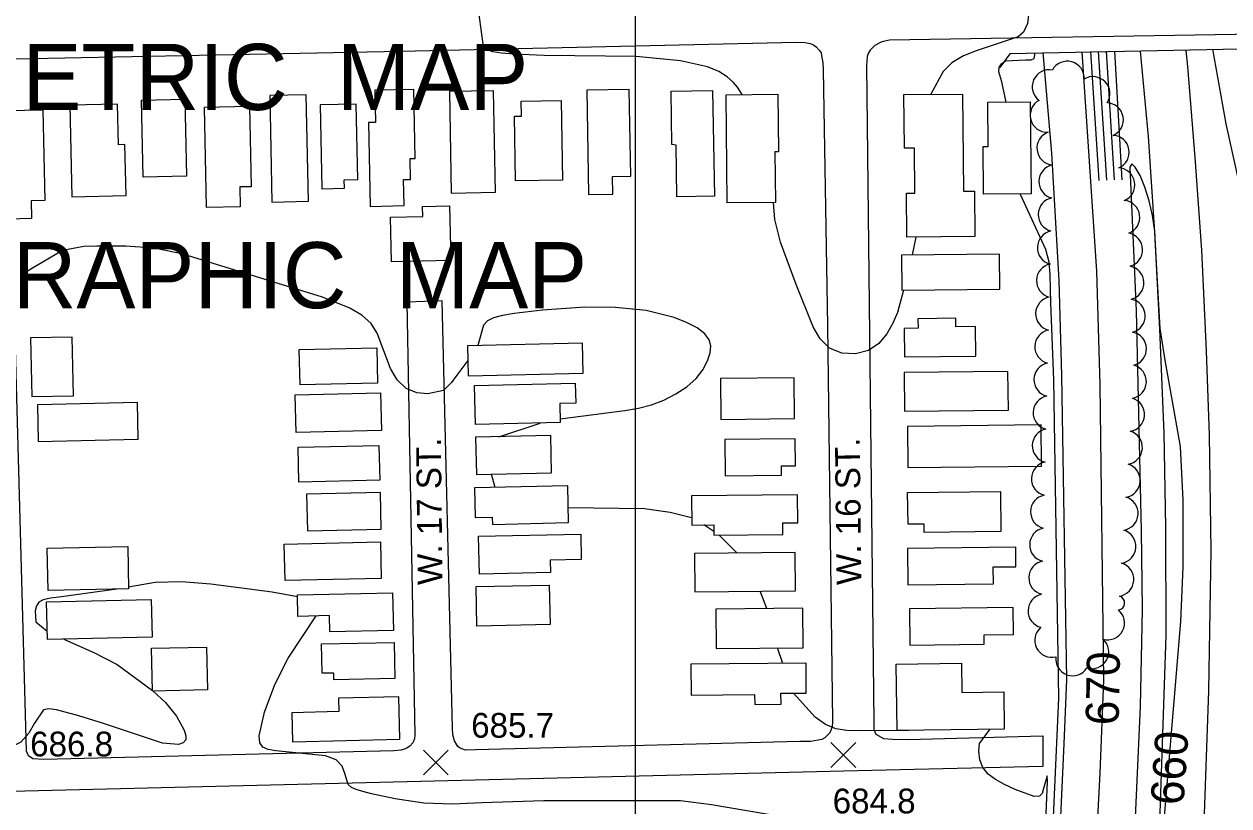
# Model space of a CAD drawing. Extents: x 79600 to 91800, y 75600 to 84400.
# Drawn here: x 85630 to 86359, y 78239 to 78712 of the extents above; entities that cross this region are included whole.
import ezdxf

# ---------------------------------------------------------------- set-up
doc = ezdxf.new("R2010")
doc.units = 0
for name, color, linetype in [('080-085$0$TI_PLAN', 7, 'Continuous'), ('080-085$0$TI_TOPO', 7, 'Continuous'), ('080-090$0$BLDG', 7, 'Continuous'), ('080-090$0$BRIDGE', 7, 'Continuous'), ('080-090$0$GRID', 7, 'Continuous'), ('080-090$0$INDEX', 7, 'Continuous'), ('080-090$0$INDXLBL', 7, 'Continuous'), ('080-090$0$INTER', 7, 'Continuous'), ('080-090$0$INTERSTATE', 7, 'Continuous'), ('080-090$0$ROAD', 7, 'Continuous'), ('080-090$0$ROAD-NAME', 7, 'Continuous'), ('080-090$0$SPOTMARK', 7, 'Continuous'), ('080-090$0$SPOTS', 7, 'Continuous'), ('080-090$0$TREES', 7, 'Continuous')]:
    doc.layers.add(name, color=color, linetype=linetype)

# ---------------------------------------------------------------- blocks, each defined once
blk = doc.blocks.new('080-090$0$SPOTS')
at = {"layer": '080-090$0$SPOTMARK'}
for p, q in [((-0.5, -0.5), (0.5, 0.5)), ((-0.5, 0.5), (0.5, -0.5))]:
    blk.add_line(p, q, dxfattribs=at)

msp = doc.modelspace()

# ---------------------------------------------------------------- linework, layer by layer
at = {"layer": '080-090$0$BLDG'}
for points in [[(85702.18, 78619.28), (85701.16, 78665.91), (85727.35, 78666.48), (85728.38, 78619.86)], [(85802.21, 78604.7), (85800.91, 78669.22), (85778.78, 78668.77), (85780.08, 78604.26)], [(85842.82, 78652.41), (85838.51, 78652.31), (85839.64, 78601.61), (85860.17, 78602.07), (85859.82, 78617.82), (85864.03, 78617.92), (85863.75, 78630.63), (85866.84, 78630.69), (85865.91, 78672.48), (85842.38, 78671.96)], [(85915.35, 78610.18), (85914.31, 78671.67), (85887.55, 78671.22), (85888.59, 78609.73)], [(85986.48, 78609.04), (85986.3, 78619.7), (85997.26, 78619.89), (85996.37, 78672.48), (85970.7, 78672.05), (85971.77, 78608.79)], [(86025.2, 78607.48), (86024.68, 78638.74), (86022.23, 78639.15), (86021.69, 78671.45), (86046.85, 78671.87), (86047.93, 78607.87)], [(86055.64, 78603.76), (86054.98, 78669.19), (86086.28, 78669.5), (86086.63, 78634.63), (86084.55, 78634.61), (86084.86, 78604.06)], [(86198.59, 78610.86), (86205.24, 78610.93), (86205.52, 78583.37), (86164.45, 78582.96), (86164.18, 78609.67), (86169.22, 78609.72), (86168.95, 78636.96), (86162.92, 78636.9), (86162.6, 78669.3), (86197.99, 78669.66)], [(85634.41, 78604.98), (85634.64, 78594.25), (85620.65, 78593.95), (85619.21, 78659.68), (85641.38, 78660.16), (85642.59, 78605.16)], [(85691.13, 78639.01), (85687.25, 78638.93), (85686.71, 78663.52), (85657.74, 78662.89), (85658.95, 78607.41), (85691.81, 78608.12)], [(85767.63, 78613.54), (85760.67, 78613.39), (85760.93, 78601.42), (85740.53, 78600.97), (85739.2, 78661.71), (85766.56, 78662.31)], [(85823.98, 78612.57), (85823.88, 78617.8), (85832.06, 78617.96), (85831.14, 78663.5), (85809.38, 78663.06), (85810.4, 78612.3)], [(85926.96, 78656.16), (85931.14, 78656.23), (85930.99, 78665.26), (85955.14, 78665.67), (85955.95, 78617.5), (85927.62, 78617.02)], [(86210.49, 78637.8), (86213.7, 78637.83), (86213.42, 78664.67), (86239.08, 78664.93), (86239.64, 78609.22), (86210.78, 78608.93)], [(85851.94, 78595.05), (85871.36, 78595.48), (85871.23, 78601.61), (85887.68, 78601.97), (85888.41, 78568.91), (85852.54, 78568.11)], [(86220.37, 78572.79), (86161.1, 78572.19), (86161.31, 78550.85), (86220.59, 78551.45)], [(86194.02, 78528.74), (86193.97, 78533.89), (86171.09, 78533.66), (86171.15, 78527.82), (86162.83, 78527.74), (86163.01, 78510.55), (86206.17, 78510.99), (86205.98, 78528.86)], [(85659.97, 78487.01), (85659.2, 78522.55), (85634.04, 78522), (85634.82, 78486.46)], [(85797.15, 78493.6), (85796.67, 78514.9), (85843.54, 78515.94), (85844.01, 78494.64)], [(85898.78, 78499.15), (85968.49, 78500.7), (85968.09, 78518.78), (85898.38, 78517.23)], [(86225.81, 78478.32), (86225.58, 78501.71), (86162.73, 78501.07), (86162.96, 78477.68)], [(85963.73, 78494.66), (85964, 78482.47), (85954.26, 78482.26), (85954.51, 78470.73), (85903.25, 78469.59), (85902.73, 78493.3)], [(86051.62, 78497.48), (86051.87, 78472.69), (86096.39, 78473.14), (86096.14, 78497.93)], [(85794.26, 78487.55), (85845.86, 78488.69), (85846.37, 78465.95), (85794.76, 78464.8)], [(85699.2, 78460.69), (85698.71, 78482.9), (85638.2, 78481.58), (85638.69, 78459.37)], [(86245.66, 78469.38), (86164.77, 78468.42), (86165.07, 78443.48), (86245.96, 78444.43)], [(85903.41, 78461.86), (85903.91, 78439.34), (85949.41, 78440.35), (85948.91, 78462.87)], [(85795.96, 78455.78), (85844.9, 78456.86), (85845.37, 78435.86), (85796.43, 78434.77)], [(86054.15, 78460.56), (86054.38, 78438.52), (86088.56, 78438.86), (86088.5, 78444.55), (86096.95, 78444.64), (86096.79, 78460.99)], [(85801.13, 78427.52), (85801.62, 78405.3), (85846.27, 78406.3), (85845.77, 78428.51)], [(85903.02, 78413.31), (85913.46, 78413.55), (85913.56, 78409.16), (85959.62, 78410.18), (85959.12, 78432.42), (85902.62, 78431.16)], [(86034.01, 78426.39), (86034.19, 78408.76), (86047.59, 78408.9), (86047.65, 78402.65), (86089.41, 78403.07), (86089.34, 78410.05), (86098.39, 78410.14), (86098.22, 78427.04)], [(86174.87, 78409.33), (86165.09, 78409.21), (86164.87, 78428.38), (86221.03, 78429.04), (86221.32, 78404.83), (86174.93, 78404.28)], [(85788.1, 78375.13), (85787.61, 78397.22), (85845.75, 78398.51), (85846.24, 78376.42)], [(85966.97, 78403.3), (85967.31, 78387.87), (85948.45, 78387.45), (85948.61, 78379.96), (85905.73, 78379.01), (85905.22, 78401.93)], [(85693.39, 78370.09), (85644.6, 78369.02), (85644.04, 78394.65), (85692.83, 78395.72)], [(86036.06, 78368.38), (86096.98, 78368.99), (86096.75, 78392.21), (86035.82, 78391.59)], [(86216.63, 78383.36), (86230.44, 78383.52), (86230.3, 78395.3), (86164.72, 78394.53), (86164.98, 78372.57), (86216.75, 78373.19)], [(85815.24, 78344.13), (85815.03, 78353.88), (85795.79, 78353.45), (85795.5, 78366.48), (85853.13, 78367.76), (85853.64, 78344.98)], [(85948.46, 78348.51), (85904.19, 78347.53), (85903.66, 78371.44), (85947.93, 78372.42)], [(85707.56, 78340.9), (85644.25, 78339.51), (85643.75, 78362.3), (85707.06, 78363.68)], [(86049.04, 78333.94), (86101.67, 78334.47), (86101.43, 78358.4), (86048.79, 78357.87)], [(86211.09, 78342.2), (86228.9, 78342.41), (86228.71, 78358.73), (86166.03, 78357.99), (86166.29, 78336.02), (86211.15, 78336.55)], [(85740.56, 78334.84), (85741.12, 78308.97), (85707.81, 78308.24), (85707.24, 78334.11)], [(85817.61, 78314.97), (85817.52, 78319.14), (85810.44, 78318.98), (85810.05, 78336.74), (85854.08, 78337.72), (85854.57, 78315.79)], [(86033.93, 78305.69), (86072.25, 78306.08), (86072.31, 78300.06), (86088.24, 78300.22), (86088.18, 78306.87), (86103.55, 78307.03), (86103.36, 78325.16), (86033.74, 78324.46)], [(86197.43, 78325.04), (86197.64, 78307.4), (86223.06, 78307.7), (86223.33, 78285.12), (86158.45, 78284.35), (86157.98, 78324.58)], [(85820.42, 78303.97), (85820.61, 78295.77), (85792.24, 78295.14), (85792.63, 78277.59), (85857.5, 78279.03), (85856.93, 78304.78)]]:
    msp.add_lwpolyline(points, close=True, dxfattribs=at)
at = {"layer": '080-090$0$BRIDGE'}
for p, q in [((86623.82, 78701.76), (86226.67, 78694.01)), ((86226.67, 78694.01), (86220.73, 78685.65))]:
    msp.add_line(p, q, dxfattribs=at)
at = {"layer": '080-090$0$GRID'}
msp.add_line((86000, 80000), (86000, 76000), dxfattribs=at)
at = {"layer": '080-090$0$INDEX'}
for points in [[(86230.22, 77938.3), (86238.56, 77989.05), (86243.86, 78033.38), (86249.82, 78105.75), (86255.81, 78192.74), (86259.7, 78276.39), (86261.25, 78315.15), (86258.1, 78499.28), (86256.59, 78556.67), (86252.05, 78633.88), (86246.94, 78694.76)], [(86252.2, 77938.77), (86258.09, 77976.03), (86264.53, 78026.54), (86271.41, 78100.25), (86277.55, 78185.24), (86281.43, 78258.63), (86283.6, 78314.81), (86281.35, 78493.63), (86279.29, 78562.36), (86270.57, 78695.23)], [(86318.19, 78205.69), (86330.25, 78350.43), (86331.66, 78383.39), (86331.59, 78423.71), (86329.93, 78456.31), (86320.7, 78508.51), (86317.65, 78527.65), (86315.44, 78567.14), (86314.53, 78586.68), (86313.15, 78596.11), (86311.09, 78605.05), (86308.49, 78613.26), (86305.52, 78620.34), (86302.67, 78625.38), (86300.5, 78627.32), (86299.42, 78625.45), (86303.27, 78538.44), (86306.2, 78405.41), (86306.82, 78357.56), (86305.5, 78298.81), (86302.64, 78231.74)]]:
    msp.add_lwpolyline(points, dxfattribs=at)
at = {"layer": '080-090$0$INTER'}
for p, q in [((86280.83, 78617.36), (86275.72, 78695.33)), ((86285.45, 78617.49), (86280.47, 78695.43)), ((86289.99, 78617.62), (86285.14, 78695.52)), ((86290.02, 78695.62), (86294.52, 78617.75)), ((86169.9, 78583.01), (86167.61, 78572.26)), ((85917.53, 78462.17), (85942.5, 78470.46)), ((85915.25, 78431.44), (85913.02, 78439.54)), ((86047.63, 78404.82), (86041.59, 78408.84)), ((86061.41, 78391.85), (86050.85, 78402.68)), ((86079.66, 78358.18), (86075.57, 78368.78)), ((86089.23, 78325.02), (86086.14, 78334.32))]:
    msp.add_line(p, q, dxfattribs=at)
for points in [[(86240.53, 78751.75), (86237.95, 78755.77), (86234.3, 78759.39), (86232.75, 78760.23), (86231.52, 78760.02), (86229.98, 78755.88), (86230.77, 78749.73), (86234.85, 78744.81), (86236.92, 78739.66), (86238.18, 78731.07), (86238.37, 78721.05), (86237.33, 78712.35), (86234.98, 78707.01), (86231.67, 78704.34), (86206.38, 78695.78), (86198.65, 78692.75), (86191.64, 78688.59), (86186.34, 78683.19), (86178.82, 78669.47)], [(86064.69, 78669.28), (86061.85, 78673.77), (86059.37, 78676.72), (86055.67, 78680.12), (86050.52, 78683.38), (86043.83, 78686.03), (86027.45, 78689.64), (86000.52, 78692.28), (85944.92, 78692.96), (85926.6, 78693.86), (85919.12, 78694.43), (85913.74, 78695.1), (85910.16, 78696.61), (85907.86, 78699.91), (85904.54, 78725.16)], [(86369.99, 78595.94), (86357.6, 78651.51), (86349.66, 78696.8)], [(86224.54, 78664.78), (86221.79, 78677.06), (86220.16, 78683.11), (86220.32, 78685.61), (86221.63, 78687.88), (86224.08, 78689.68), (86236.15, 78690.44), (86239.56, 78690.44), (86241.41, 78691.24), (86242.12, 78694.67)], [(86225.65, 77938.21), (86233, 77981.26), (86238.78, 78025.46), (86251.15, 78186.91), (86256.46, 78304.03), (86253.44, 78496.7), (86251.58, 78543.26), (86251.12, 78560.21), (86250.43, 78567.89), (86248.58, 78575.55), (86232.97, 78609.16)], [(86162.44, 78550.86), (86158.64, 78537.47), (86155.98, 78530.95), (86152.32, 78524.42), (86147.44, 78518.65), (86141.09, 78514.41), (86133.27, 78512.35), (86125, 78512.75), (86117.55, 78515.76), (86111.87, 78521.36), (86107.6, 78528.81), (86097.36, 78554.3), (86087.83, 78580.02), (86084.39, 78593.68), (86083.73, 78604.04)], [(85898.58, 78508.37), (85891.5, 78498.73), (85888.71, 78494.97), (85883.92, 78490.17), (85874.53, 78488.21), (85867.86, 78488.8), (85861.36, 78491.43), (85856, 78496.58), (85851.84, 78503.47), (85843.79, 78524.93), (85840.09, 78530.83), (85834.49, 78535.86), (85827.34, 78540.11), (85810.7, 78546.74), (85743.93, 78567.35), (85726.35, 78572.75), (85708.84, 78576.31), (85691.6, 78577.62), (85674.2, 78577.65), (85666.35, 78577.25), (85653.31, 78574.97), (85634.18, 78563.63), (85628.62, 78560.05)], [(85954.46, 78472.96), (85993.72, 78478.02), (86001.91, 78479.55), (86009.76, 78481.6), (86017.33, 78484.4), (86024.6, 78488.07), (86031.24, 78492.49), (86036.81, 78497.47), (86040.98, 78502.78), (86043.8, 78508.07), (86045.4, 78512.97), (86045.83, 78517.2), (86044.84, 78520.94), (86042.09, 78524.48), (86037.38, 78528.03), (86031.05, 78531.41), (86023.57, 78534.39), (86006.59, 78538.53), (85987.99, 78540.45), (85969.41, 78540.61), (85943.8, 78538.73), (85926.76, 78536.72), (85919.63, 78535.54), (85914.31, 78534.18), (85910.61, 78532.38), (85908.15, 78529.81), (85904.81, 78517.38)], [(86034.14, 78413.01), (86021.2, 78416.32), (86005.55, 78418.53), (85959.42, 78419.12)], [(85686.33, 78369.94), (85652.7, 78365.35), (85646.03, 78364.39), (85641.62, 78363.38), (85639.07, 78362.01), (85637.65, 78359.89), (85636.78, 78356.83), (85637.19, 78350.12), (85644.14, 78344.5)], [(85795.53, 78365.36), (85780.25, 78368.11), (85743.19, 78372.97), (85725.41, 78374.29), (85709.34, 78373.92), (85693.37, 78371.12)], [(86119.84, 78226.91), (86046.19, 78239.29), (86027.39, 78241.81), (85944.71, 78241.79), (85907.16, 78240.51), (85889.46, 78239.83), (85872.09, 78240.43), (85854.67, 78242.92), (85840.38, 78245.97), (85835.14, 78247.36), (85831.13, 78248.65), (85828.26, 78249.93), (85826.33, 78251.66), (85824.24, 78258.3), (85822.59, 78262.72), (85818.94, 78266.54), (85812.5, 78269), (85782.5, 78271.97), (85777.85, 78272.81), (85774.63, 78274.24), (85772.85, 78276.82), (85772.48, 78281.16), (85775.57, 78295.52), (85781.82, 78312.19), (85789.95, 78328.06), (85806.91, 78353.7)], [(85654.07, 78339.73), (85672.63, 78331.46), (85686.44, 78324.3), (85707.8, 78308.6)], [(85708.2, 78308.24), (85715.67, 78301.25), (85722.35, 78293.04), (85727.09, 78284.52), (85728.08, 78281.19), (85727.92, 78278.67), (85726.47, 78276.93), (85723.64, 78275.97), (85713.94, 78276.7), (85678.16, 78288.59), (85663.24, 78293.26), (85649.65, 78296.86), (85645.1, 78297.56), (85641.82, 78296.83), (85636.36, 78288.83), (85632.88, 78282.66), (85628.07, 78277.3), (85621.61, 78274.13), (85614.25, 78273.03), (85607.06, 78273.48), (85590.45, 78279.78)], [(86165.64, 78284.44), (86135.58, 78284.08), (86128.13, 78284.38), (86121.41, 78285.45), (86115.09, 78288), (86108.97, 78292.38), (86095.79, 78306.95)], [(86221.35, 77938.11), (86228.15, 77976.59), (86233.82, 78019.03), (86241.39, 78110.53), (86246.5, 78187.89), (86248.85, 78238.77), (86249.49, 78253.74), (86249.37, 78257.02), (86247.09, 78249.22), (86246.19, 78246.21), (86244.62, 78244.56), (86241.51, 78244.47), (86229.96, 78248.58), (86223.5, 78251.63), (86217.97, 78254.68), (86213.6, 78257.95), (86210.47, 78261.88), (86208.61, 78266.69), (86207.96, 78271.81), (86208.43, 78276.43), (86214.55, 78285.02)]]:
    msp.add_lwpolyline(points, dxfattribs=at)
at = {"layer": '080-090$0$INTERSTATE'}
for p, q in [((86305.56, 78695.55), (86310.52, 78643.98)), ((86334.43, 78686.4), (86333.46, 78696.09)), ((86338.85, 78631.22), (86334.43, 78686.4)), ((86310.52, 78643.98), (86314.2, 78586.04)), ((86342.97, 78575.21), (86338.85, 78631.22)), ((86314.2, 78586.04), (86317.31, 78527.27)), ((86345.77, 78514.09), (86342.97, 78575.21)), ((86317.31, 78527.27), (86319.95, 78464.64)), ((86347.49, 78463.24), (86345.77, 78514.09)), ((86319.95, 78464.64), (86321.01, 78407.29)), ((86348.49, 78393.3), (86347.49, 78463.24)), ((86321.01, 78407.29), (86321.11, 78341.92)), ((86347.18, 78308.29), (86348.49, 78393.3)), ((86321.11, 78341.92), (86316.85, 78217.77)), ((86344.06, 78222.06), (86347.18, 78308.29))]:
    msp.add_line(p, q, dxfattribs=at)
at = {"layer": '080-090$0$ROAD'}
for p, q in [((86632.12, 78710.35), (86153.96, 78702.19)), ((85367.27, 78685.75), (85858.06, 78695.52)), ((85858.06, 78695.52), (86097.58, 78700.98)), ((86097.58, 78700.98), (86102.84, 78700.76)), ((86102.84, 78700.76), (86105.88, 78700.16)), ((86105.88, 78700.16), (86107.94, 78699.44)), ((86107.94, 78699.44), (86109.59, 78698.3)), ((86109.59, 78698.3), (86111.35, 78696.2)), ((86111.35, 78696.2), (86112.44, 78694.66)), ((86142.1, 78696.14), (86140.96, 78694.22)), ((86144.91, 78699.01), (86142.1, 78696.14)), ((86147.56, 78700.49), (86144.91, 78699.01)), ((86149.24, 78701.16), (86147.56, 78700.49)), ((86153.96, 78702.19), (86149.24, 78701.16)), ((86112.44, 78694.66), (86112.83, 78692.99)), ((86112.83, 78692.99), (86113.59, 78688.55)), ((86113.59, 78688.55), (86113.66, 78684.25)), ((86140.37, 78692.29), (86139.87, 78686.62)), ((86140.96, 78694.22), (86140.37, 78692.29)), ((86113.66, 78684.25), (86116.27, 78529.25)), ((86139.87, 78686.62), (86144.43, 78289.39)), ((85883.16, 78544.47), (85861.68, 78543.55)), ((85861.68, 78543.55), (85866.52, 78281.75)), ((85889.43, 78285.83), (85883.16, 78544.47)), ((85631.34, 78279.27), (85624.37, 78537.5)), ((86116.27, 78529.25), (86119.37, 78289.91)), ((86119.37, 78289.91), (86119.18, 78286.59)), ((86144.43, 78289.39), (86144.5, 78284.95)), ((85866.52, 78281.75), (85866.48, 78279.25)), ((85889.51, 78281.81), (85889.43, 78285.83)), ((85890.7, 78278.19), (85889.51, 78281.81)), ((86114.79, 78279.87), (86112.97, 78278.93)), ((86117.74, 78283.01), (86114.79, 78279.87)), ((86119.18, 78286.59), (86117.74, 78283.01)), ((86144.5, 78284.95), (86145.71, 78282.16)), ((86145.71, 78282.16), (86150.24, 78279.6)), ((86150.24, 78279.6), (86155.77, 78279.1)), ((86165.04, 78278.96), (86246.78, 78281.17)), ((86246.78, 78281.17), (86246.77, 78262.61)), ((85631.64, 78271.92), (85631.34, 78279.27)), ((85858.07, 78272.46), (85853.91, 78272.11)), ((85860.29, 78273.12), (85858.07, 78272.46)), ((85861.97, 78273.78), (85860.29, 78273.12)), ((85863.65, 78274.87), (85861.97, 78273.78)), ((85865.48, 78276.91), (85863.65, 78274.87)), ((85866.48, 78279.25), (85865.48, 78276.91)), ((85892.05, 78275.68), (85890.7, 78278.19)), ((85892.72, 78274.7), (85892.05, 78275.68)), ((85893.95, 78273.71), (85892.72, 78274.7)), ((85897.26, 78272.55), (85893.95, 78273.71)), ((85903.22, 78272.74), (85897.26, 78272.55)), ((86099.52, 78277.61), (85903.22, 78272.74)), ((86106.31, 78277.65), (86099.52, 78277.61)), ((86112.97, 78278.93), (86106.31, 78277.65)), ((86155.77, 78279.1), (86165.04, 78278.96)), ((85632.71, 78269), (85631.64, 78271.92)), ((85635.45, 78267.29), (85632.71, 78269)), ((85642.09, 78266.78), (85635.45, 78267.29)), ((85853.91, 78272.11), (85642.09, 78266.78)), ((86134.56, 78259.9), (85517.67, 78244.87)), ((86246.77, 78262.61), (86134.56, 78259.9))]:
    msp.add_line(p, q, dxfattribs=at)
at = {"layer": '080-090$0$TREES'}
for centre, radius, start, end in [((86261.48, 78679.25), 10.25, 356.92697, 151.5662), ((86250.5, 78674.07), 10.25, 78.95686, 233.59609), ((86277.03, 78669.94), 10.25, 326.57633, 121.21556), ((86249.3, 78656.81), 10.25, 118.43649, 273.07572), ((86285.2, 78654.05), 10.25, 293.20217, 87.84141), ((86253.36, 78636.94), 10.25, 110.01511, 264.65434), ((86288.71, 78634.39), 10.25, 292.44075, 87.07998), ((86254.52, 78616.71), 10.25, 101.94264, 256.58188), ((86292.1, 78614.68), 10.25, 292.44075, 87.07998), ((86254.14, 78596.69), 10.25, 101.20124, 255.84047), ((86295.13, 78595), 10.25, 290.3893, 85.02853), ((86253.62, 78576.69), 10.25, 101.20124, 255.84047), ((86296.84, 78575.31), 10.25, 284.91048, 79.54971), ((86253.1, 78556.7), 10.25, 101.20124, 255.84047), ((86297.62, 78555.32), 10.25, 284.91048, 79.54971), ((86252.59, 78536.71), 10.25, 101.20124, 255.84047), ((86298.39, 78535.34), 10.25, 284.91048, 79.54971), ((86252.07, 78516.71), 10.25, 101.20124, 255.84047), ((86299.17, 78515.35), 10.25, 284.91048, 79.54971), ((86251.56, 78496.72), 10.25, 101.20124, 255.84047), ((86299.11, 78495.56), 10.25, 280.08902, 74.72825), ((86251.04, 78476.73), 10.25, 101.20124, 255.84047), ((86298.01, 78475.64), 10.25, 278.94596, 73.58519), ((86250.52, 78456.73), 10.25, 101.20124, 255.84047), ((86296.71, 78455.68), 10.25, 278.94596, 73.58519), ((86250.01, 78436.74), 10.25, 101.20124, 255.84047), ((86295.4, 78435.72), 10.25, 278.94596, 73.58519), ((86249.49, 78416.75), 10.25, 101.20124, 255.84047), ((86294.1, 78415.76), 10.25, 278.94596, 73.58519), ((86248.97, 78396.75), 10.25, 101.20124, 255.84047), ((86292.8, 78395.81), 10.25, 278.94596, 73.58519), ((86248.46, 78376.76), 10.25, 101.20124, 255.84047), ((86291.5, 78375.85), 10.25, 278.94596, 73.58519), ((86247.97, 78356.77), 10.25, 101.35495, 255.99418), ((86291.87, 78361.58), 4.32, 278.94596, 73.58519), ((86285.9, 78349.51), 10.25, 254.98341, 49.62265), ((86252.04, 78338.94), 10.25, 129.70906, 284.34829), ((86276.36, 78332.02), 10.25, 253.14082, 47.78005), ((86264.75, 78327.73), 10.25, 172.80588, 327.44512)]:
    msp.add_arc(centre, radius, start, end, dxfattribs=at)

# ---------------------------------------------------------------- block references
at = {"layer": '080-090$0$SPOTMARK', "xscale": 15, "yscale": 15}
for p in [(85879.35, 78264.99), (86125.93, 78269.51)]:
    msp.add_blockref('080-090$0$SPOTS', p, dxfattribs=at)

# ---------------------------------------------------------------- texts
at = {"layer": '080-085$0$TI_PLAN'}
msp.add_text('PLANIMETRIC  MAP', height=40, dxfattribs=at).set_placement((85430, 78660))
at = {"layer": '080-085$0$TI_TOPO'}
msp.add_text('TOPOGRAPHIC  MAP', height=40, dxfattribs=at).set_placement((85430, 78540))
at = {"layer": '080-090$0$INDXLBL'}
for s, rotation, p in [('670', 88.8581, (86292.54, 78287.41)), ('660', 85.98742, (86331.8, 78238.78))]:
    msp.add_text(s, height=20, rotation=rotation, dxfattribs=at).set_placement(p)
at = {"layer": '080-090$0$ROAD-NAME'}
for s, p in [('W. 17 ST.', (85883.37, 78372.58)), ('W. 16 ST.', (86136.89, 78372.55))]:
    msp.add_text(s, height=15, rotation=90.65918, dxfattribs=at).set_placement(p)
at = {"layer": '080-090$0$SPOTS'}
for s, p in [('685.7', (85900.7, 78279.99)), ('686.8', (85633.77, 78268.68)), ('684.8', (86119.5, 78234.18))]:
    msp.add_text(s, height=15, dxfattribs=at).set_placement(p)

doc.saveas('drawing.dxf')
